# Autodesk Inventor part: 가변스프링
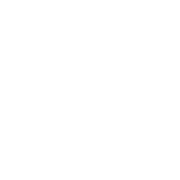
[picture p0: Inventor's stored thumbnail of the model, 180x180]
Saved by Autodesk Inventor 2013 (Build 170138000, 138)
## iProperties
Created: 2018-10
Part Number: 가변스프링
Material: 일반
Document SubType Name: Modeling
Designer: Administrator
Density: 1 g/cm^3
Mass: 0.776189 g
Surface Area: 15.7652 cm^2
Volume: 0.776189 cm^3
Author: Administrator
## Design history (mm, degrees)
sketch "스케치1"
  geometry: L1 (0, 0)-(0, 25.77); L2 (0, 0)-(8, 0); L3 (0, 25.77)-(8, 25.77); C1 r 1 at (8, 0)
  constraints: 6 end point, 1 centre point, 1 coincident, 1 parallel, 1 perpendicular, 1 vertical
  dimensions: "d0" = 25.76996 distance of L1.start L1.end (derived); "d1" = 8 distance of L1.start L2.end; "d2" = 2 diameter of C1; "d3" = 8 distance of L1.end L3.end
feature "코일1" pitch "d4" = 10; turns "d6" = 5; dims "d5" = 25.76996 (= d0), "d7" = 0, angle "d8" = 90 deg, angle "d9" = 90 deg, "d10" = 0, "d11" = 0
sketch "스케치2"
  geometry: L1 (25.77, 11)-(0, 11); L2 (0, 11)-(0, -11); L3 (0, -11)-(25.77, -11); L4 (25.77, -11)-(25.77, 11); 2 further points
  constraints: 8 end point, 2 parallel, 1 coincident, 1 horizontal, 1 midpoint, 1 perpendicular
  dimensions: "d12" = 25.76996 distance of L1.start L1.end (derived); "d14" = 22 distance of L3.end L1.start
extrude "돌출1" sketch "스케치2" stored distance "d15" = 0; taper "d16" = 0 deg
node "솔리드1"
